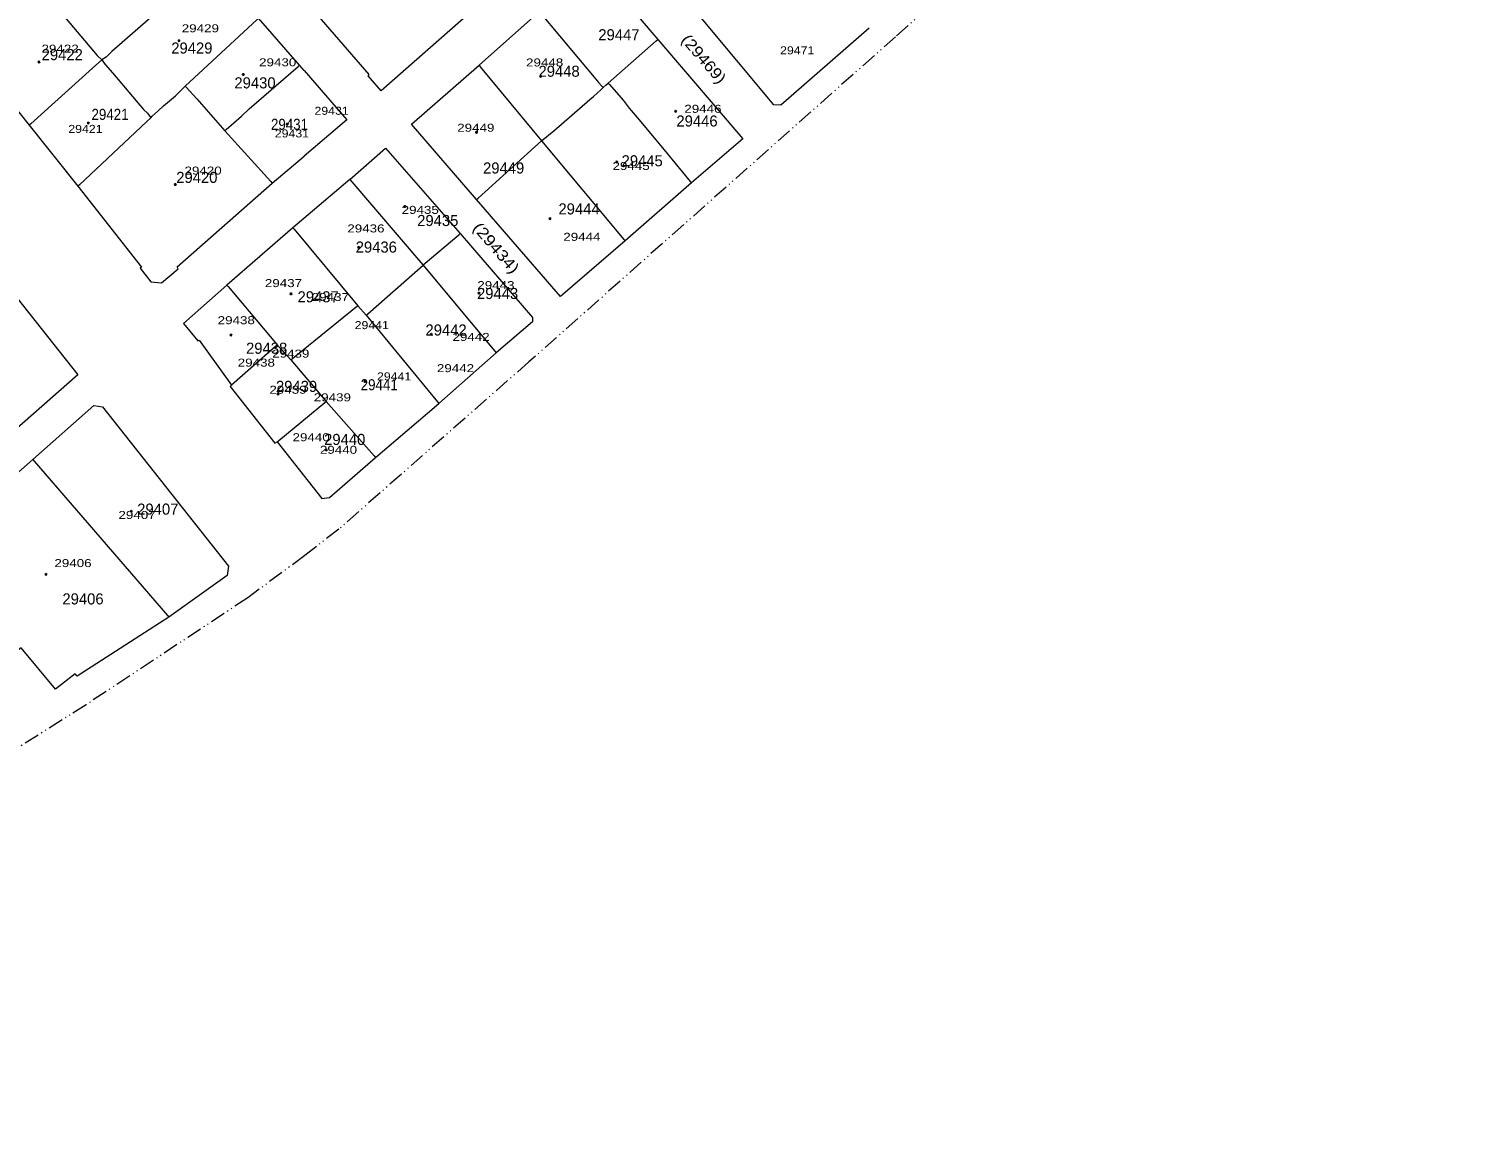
# Model space of a CAD drawing. Extents: x 650553 to 652508, y 239277 to 241647.
# Drawn here: x 651285.4 to 651750.1, y 239749.9 to 240108.2 of the extents above; entities that cross this region are included whole.
import ezdxf

# ---------------------------------------------------------------- set-up
doc = ezdxf.new("R2010")
doc.units = 0
doc.header["$PDMODE"] = 32
doc.header["$PDSIZE"] = 0.5
doc.linetypes.add('DASH_DOUBLE_DOT', pattern=[9.2, 5, -1.2, 0.3, -1.2, 0.3, -1.2])
for name, color, linetype in [('19', 7, 'Continuous'), ('20', 7, 'Continuous'), ('6', 7, 'Continuous')]:
    doc.layers.add(name, color=color, linetype=linetype)
for name, color, linetype, lineweight in [('3', 7, 'Continuous', 13), ('5', 7, 'Continuous', 13), ('52', 7, 'DASH_DOUBLE_DOT', 13)]:
    doc.layers.add(name, color=color, linetype=linetype, lineweight=lineweight)

msp = doc.modelspace()

# ---------------------------------------------------------------- linework, layer by layer
at = {"layer": '3'}
msp.add_line((651301.48, 239995.66), (651269.84, 239967.99), dxfattribs=at)
for points in [[(651375, 240094.57), (651373.49, 240096.32), (651360.19, 240111.6), (651345.04, 240129.24), (651330.47, 240146.6), (651315.74, 240163.7), (651302.02, 240179.87)], [(651459.75, 240140.58), (651399.97, 240087.93), (651395.8, 240092.84), (651396.15, 240093.24), (651375, 240117.7)], [(651558.55, 240108.32), (651529.89, 240083.28), (651527.6, 240083.46), (651504.61, 240110.95), (651480.3, 240139.14)], [(651244.93, 240128.08), (651253.33, 240117.93), (651267.91, 240098.88), (651285.64, 240076.82), (651301.47, 240056.95)], [(651451.4, 240113.72), (651468.29, 240128.9), (651469.42, 240128.69), (651489.89, 240104.65)], [(651409.9, 240077.1), (651431.81, 240096.29), (651451.4, 240113.72)], [(651217.69, 240101.92), (651225.95, 240091.72), (651240.57, 240073.58), (651254.7, 240055.63), (651273.8, 240030.45), (651301.48, 239995.66)], [(651489.89, 240104.65), (651517.56, 240072.4), (651500.82, 240058.03), (651479.31, 240039.19)], [(651375, 240094.57), (651388.89, 240078.53), (651375, 240066.77)], [(651479.31, 240039.19), (651458.28, 240021.13), (651431.02, 240052.7), (651409.9, 240077.1)], [(651389.78, 240059.21), (651401.44, 240069.38), (651425.7, 240041.6)], [(651301.47, 240056.95), (651322.14, 240030.72), (651321.68, 240030.35), (651325.19, 240025.92), (651328.59, 240025.54), (651334.08, 240030.09), (651333.73, 240030.74), (651364.61, 240057.97), (651375, 240066.77)], [(651389.78, 240059.21), (651371.34, 240043.48), (651349.81, 240024.87)], [(651425.7, 240041.6), (651449.14, 240014.38), (651449.21, 240012.93), (651437.36, 240002.88)], [(651349.81, 240024.87), (651335.79, 240012.34), (651340.39, 240006.7), (651340.85, 240007.02), (651351.42, 239992.36)], [(651366.25, 239973.93), (651380.71, 239955.53), (651383.21, 239955.85), (651398.13, 239968.9), (651418.7, 239986.4), (651437.36, 240002.88)], [(651351.42, 239992.36), (651350.88, 239991.96), (651365.49, 239973.53), (651366.25, 239973.93)], [(651286.79, 239968.16), (651306.6, 239985.78), (651309.5, 239985.34)], [(651309.5, 239985.34), (651350.37, 239933.5), (651349.93, 239930.52), (651331.02, 239916.99)], [(651294.154, 239893.589), (651283.07, 239907.03), (651281.72, 239905.99), (651265.26, 239925.42), (651266.66, 239926.6), (651255.322, 239940.281), (651261.29, 239944.93), (651260.89, 239945.47), (651286.79, 239968.16)], [(651331.02, 239916.99), (651301.24, 239897.8), (651300.6, 239898.61), (651294.154, 239893.589)]]:
    msp.add_lwpolyline(points, dxfattribs=at)
at = {"layer": '5'}
msp.add_line((651370.6, 240000.54), (651382.16, 239987.09), dxfattribs=at)
for points in [[(651345.04, 240129.24), (651344.54, 240128.803), (651312.49, 240100.79), (651310.68, 240098.95), (651309.28, 240098.02)], [(651294.23, 240115.55), (651294.68, 240114.85), (651307.73, 240099.48), (651309.28, 240098.02)], [(651336.33, 240089.52), (651359.69, 240111.137), (651360.19, 240111.6)], [(651451.4, 240113.72), (651451.818, 240113.22), (651470.25, 240091.16), (651470.65, 240090.63), (651471.695, 240089.53), (651472.17, 240089.03)], [(651473.8, 240090.49), (651489.39, 240104.21), (651489.89, 240104.65)], [(651309.28, 240098.02), (651306.22, 240095.33), (651286.14, 240077.27), (651285.64, 240076.82)], [(651309.28, 240098.02), (651310.31, 240096.56), (651312.7, 240093.78), (651322.78, 240081.93), (651324.03, 240080.66), (651325.12, 240079.25)], [(651349.15, 240074.94), (651349.65, 240075.38), (651354.58, 240079.72), (651357.15, 240082.12), (651372.99, 240095.885), (651373.49, 240096.32)], [(651431.81, 240096.29), (651432.223, 240095.79), (651452.12, 240071.7)], [(651325.12, 240079.25), (651325.62, 240079.705), (651327.58, 240081.49), (651329.28, 240083.06), (651333.17, 240086.38), (651336.33, 240089.52)], [(651336.33, 240089.52), (651336.791, 240089.02), (651340.14, 240085.39), (651349.15, 240074.94)], [(651452.12, 240071.7), (651456.1, 240075), (651467.85, 240085.18), (651468.97, 240086.16), (651471.42, 240088.27), (651472.17, 240089.03)], [(651472.17, 240089.03), (651473.1, 240089.97), (651473.8, 240090.49)], [(651473.8, 240090.49), (651474.234, 240089.99), (651478.64, 240084.91), (651480.59, 240082.37), (651483.79, 240078.56), (651492.99, 240067.64), (651500.413, 240058.53), (651500.82, 240058.03)], [(651325.12, 240079.25), (651323.8, 240077.92), (651301.97, 240057.42), (651301.47, 240056.95)], [(651349.15, 240074.94), (651364.154, 240058.47), (651364.61, 240057.97)], [(651431.02, 240052.7), (651431.52, 240053.15), (651452.12, 240071.7)], [(651452.12, 240071.7), (651478.892, 240039.69), (651479.31, 240039.19)], [(651389.78, 240059.21), (651413.58, 240031.42), (651413.614, 240031.379), (651437.36, 240002.88)], [(651371.34, 240043.48), (651371.756, 240042.98), (651392.38, 240018.17), (651395.14, 240015.04)], [(651413.614, 240031.379), (651413.66, 240031.42), (651425.2, 240041.177), (651425.7, 240041.6)], [(651395.14, 240015.04), (651395.64, 240015.482), (651413.614, 240031.379)], [(651349.81, 240024.87), (651350.233, 240024.37), (651366.24, 240005.43), (651370.6, 240000.54)], [(651370.6, 240000.54), (651391.88, 240017.765), (651392.38, 240018.17)], [(651395.14, 240015.04), (651418.289, 239986.9), (651418.7, 239986.4)], [(651366.24, 240005.43), (651365.74, 240004.989), (651351.42, 239992.36)], [(651366.25, 239973.93), (651366.75, 239974.344), (651381.66, 239986.676), (651382.16, 239987.09)], [(651382.16, 239987.09), (651397.691, 239969.4), (651398.13, 239968.9)], [(651286.79, 239968.16), (651287.222, 239967.66), (651330.588, 239917.49), (651331.02, 239916.99)]]:
    msp.add_lwpolyline(points, dxfattribs=at)
at = {"layer": '52'}
for points in [[(651750.052, 240268.782), (651729.12, 240250.009), (651567.141, 240105.534), (651448.015, 239999.895)], [(651448.015, 239999.895), (651386.207, 239945.551), (651375.157, 239936.971)], [(651375.157, 239936.971), (651356.663, 239923.28), (651304.088, 239888.503), (651187.159, 239814.585), (651127.357, 239763.518), (651113.762, 239749.917)]]:
    msp.add_lwpolyline(points, dxfattribs=at)
at = {"layer": '6'}
for p in [(651334.343, 240104.245), (651288.828, 240097.345), (651355.182, 240093.27), (651451.861, 240092.71), (651495.672, 240081.34), (651304.858, 240077.485), (651369.455, 240077.145), (651430.983, 240074.495), (651476.564, 240064.84), (651333.099, 240057.53), (651407.688, 240050.379), (651454.857, 240046.415), (651392.659, 240037.125), (651370.708, 240022.01), (651431.8, 240022.24), (651351.188, 240008.615), (651416.277, 240008.889), (651366.476, 239989.48), (651394.726, 239993.535), (651382.162, 239971.31), (651318.78, 239951.385), (651291.069, 239930.874)]:
    msp.add_point(p, dxfattribs=at)

# ---------------------------------------------------------------- texts
at = {"layer": '19'}
for s, p in [('29447', (651470.563, 240104.388)), ('29422', (651289.672, 240097.922)), ('29429', (651331.791, 240100.077)), ('29430', (651352.308, 240088.762)), ('29448', (651451.123, 240092.534)), ('29446', (651495.941, 240076.369)), ('29449', (651433.107, 240061.101)), ('29445', (651478.121, 240063.437)), ('29420', (651333.409, 240058.049)), ('29444', (651457.602, 240047.811)), ('29435', (651411.706, 240044.04)), ('29436', (651391.728, 240035.418)), ('29437', (651372.829, 240019.253)), ('29443', (651431.144, 240020.331)), ('29442', (651414.405, 240008.476)), ('29438', (651356.089, 240002.55)), ('29439', (651365.809, 239990.157)), ('29440', (651381.467, 239972.914)), ('29407', (651320.721, 239950.284)), ('29406', (651296.423, 239921.113))]:
    msp.add_text(s, height=3.6, dxfattribs=at).set_placement(p)
for s, rotation, width, p in [('(29469)', 310.629, 1.15, (651497.266, 240104.403)), ('(29434)', 310.733, 1.2, (651429.508, 240043.308))]:
    msp.add_text(s, height=3.6, rotation=rotation, dxfattribs=dict(at, width=width)).set_placement(p)
at = {"layer": '19', "width": 0.9}
for s, p in [('29421', (651305.871, 240078.524)), ('29431', (651364.189, 240075.291)), ('29441', (651393.347, 239990.695))]:
    msp.add_text(s, height=3.6, dxfattribs=at).set_placement(p)
at = {"layer": '20'}
for s, width, p in [('29429', 1.25, (651335.203, 240106.985)), ('29422', 1.25, (651289.637, 240100.364)), ('29471', 1.15, (651529.637, 240099.824)), ('29430', 1.25, (651360.326, 240095.94)), ('29448', 1.25, (651447.085, 240095.892)), ('29431', 1.15, (651378.331, 240080.186)), ('29446', 1.25, (651498.508, 240080.833)), ('29421', 1.15, (651298.334, 240074.298)), ('29431', 1.15, (651365.448, 240072.834)), ('29449', 1.25, (651424.716, 240074.682)), ('29445', 1.25, (651475.181, 240062.265)), ('29420', 1.25, (651336.098, 240060.763)), ('29435', 1.25, (651406.657, 240047.993)), ('29436', 1.25, (651389.002, 240041.966)), ('29444', 1.25, (651459.188, 240039.241)), ('29437', 1.25, (651362.211, 240024.205)), ('29437', 1.25, (651377.443, 240019.698)), ('29443', 1.25, (651431.241, 240023.544)), ('29438', 1.25, (651346.869, 240012.155)), ('29441', 1.15, (651391.387, 240010.556)), ('29442', 1.25, (651423.173, 240006.719)), ('29439', 1.25, (651364.595, 240001.296)), ('29438', 1.25, (651353.39, 239998.373)), ('29442', 1.25, (651418.112, 239996.571)), ('29441', 1.15, (651398.637, 239993.899)), ('29439', 1.25, (651363.677, 239989.559)), ('29439', 1.25, (651378.09, 239987.086)), ('29440', 1.25, (651371.201, 239974.134)), ('29440', 1.25, (651380.094, 239970.054)), ('29407', 1.25, (651314.63, 239948.878)), ('29406', 1.25, (651293.818, 239933.246))]:
    msp.add_text(s, height=2.6, dxfattribs=dict(at, width=width)).set_placement(p)

doc.saveas('drawing.dxf')
